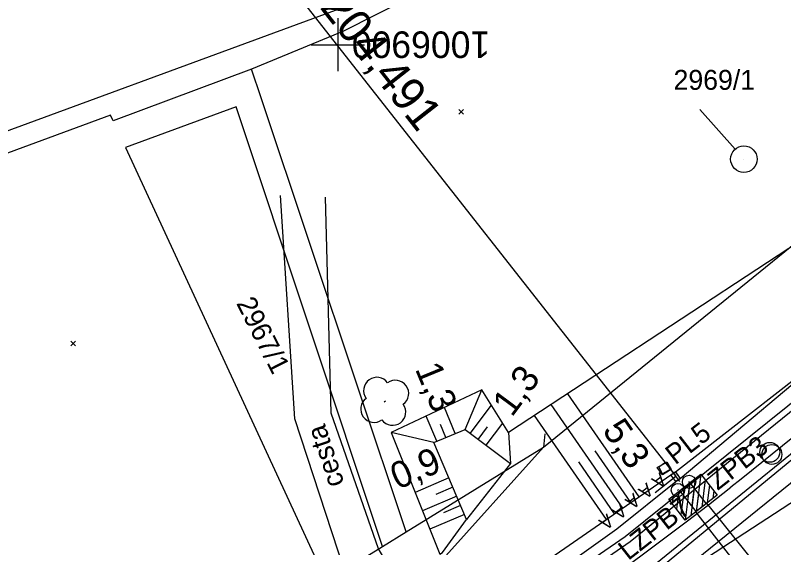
# Model space of a CAD drawing. Extents: x -800194 to -799078, y -1007177 to -1006597.
# Drawn here: x -799524.3 to -799466.4, y -1006937.9 to -1006897.8 of the extents above; entities that cross this region are included whole.
import ezdxf

# ---------------------------------------------------------------- set-up
doc = ezdxf.new("R2010")
doc.units = 0
for name, color, linetype in [('02_Osa_koleje', 7, 'Continuous'), ('_Vrstva 7 - Přesunutá', 7, 'Continuous'), ('Ramove udaje', 7, 'Continuous'), ('Vrstva 12', 7, 'Continuous'), ('Vrstva 27', 7, 'Continuous'), ('Vrstva 3', 7, 'Continuous'), ('Vrstva 37', 7, 'Continuous'), ('Vrstva 4', 7, 'Continuous'), ('Vrstva 48', 7, 'Continuous'), ('Vrstva 49', 7, 'Continuous'), ('Vrstva 50', 7, 'Continuous'), ('Vrstva 51', 7, 'Continuous'), ('Vrstva 53', 7, 'Continuous'), ('Vrstva 55', 7, 'Continuous'), ('Vrstva 56', 7, 'Continuous'), ('Vrstva 57', 7, 'Continuous'), ('Vrstva 6', 7, 'Continuous'), ('Vrstva 7', 7, 'Continuous')]:
    doc.layers.add(name, color=color, linetype=linetype)

msp = doc.modelspace()

# ---------------------------------------------------------------- linework, layer by layer
at = {"layer": '02_Osa_koleje'}
msp.add_lwpolyline([(-799465.749, -1006929.588), (-799466.523, -1006930.22), (-799467.3, -1006930.85), (-799468.078, -1006931.478), (-799468.859, -1006932.103), (-799469.642, -1006932.726), (-799470.426, -1006933.345)], dxfattribs=at)
msp.add_arc((-799651.022, -1006703.891), 292, 255.62486, 308.20516, dxfattribs=at)
at = {"layer": '_Vrstva 7 - Přesunutá'}
msp.add_circle((-799467.33, -1006930.875), 0.75, dxfattribs=at)
at = {"layer": 'Ramove udaje'}
for p, q in [((-799500, -1006898), (-799500, -1006902)), ((-799502, -1006900), (-799500, -1006900)), ((-799500, -1006900), (-799498, -1006900))]:
    msp.add_line(p, q, dxfattribs=at)
at = {"layer": 'Vrstva 12'}
for p, q in [((-799475.329, -1006931.448), (-799475.236, -1006931.455)), ((-799475.848, -1006931.802), (-799475.952, -1006931.866)), ((-799474.922, -1006932.004), (-799474.993, -1006932.013)), ((-799474.599, -1006932.171), (-799474.596, -1006932.171)), ((-799475.551, -1006932.322), (-799475.567, -1006932.408)), ((-799474.93, -1006932.406), (-799474.926, -1006932.405)), ((-799474.241, -1006932.695), (-799474.237, -1006932.694)), ((-799474.57, -1006932.917), (-799474.568, -1006932.916))]:
    msp.add_line(p, q, dxfattribs=at)
for points in [[(-799475.236, -1006931.455), (-799474.922, -1006932.004), (-799475.567, -1006932.408), (-799475.952, -1006931.866), (-799475.236, -1006931.455)], [(-799475.329, -1006931.448), (-799474.993, -1006932.013), (-799475.551, -1006932.322), (-799475.848, -1006931.802), (-799475.329, -1006931.448)], [(-799474.599, -1006932.171), (-799474.241, -1006932.695), (-799474.57, -1006932.917), (-799474.93, -1006932.406), (-799474.599, -1006932.171)], [(-799474.596, -1006932.171), (-799474.237, -1006932.694), (-799474.568, -1006932.916), (-799474.926, -1006932.405), (-799474.596, -1006932.171)]]:
    msp.add_lwpolyline(points, dxfattribs=at)
at = {"layer": 'Vrstva 27'}
for p, q in [((-799473.605, -1006932.963), (-799473.527, -1006932.901)), ((-799474.438, -1006933.585), (-799474.36, -1006933.523))]:
    msp.add_line(p, q, dxfattribs=at)
for centre in [(-799473.566, -1006932.932), (-799474.399, -1006933.554)]:
    msp.add_circle(centre, 0.5, dxfattribs=at)
at = {"layer": 'Vrstva 3'}
for p, q in [((-799473.103, -1006932.691), (-799473.352, -1006934.755)), ((-799472.686, -1006932.363), (-799473.025, -1006935.171)), ((-799473.918, -1006933.335), (-799474.181, -1006935.397)), ((-799473.499, -1006933.01), (-799473.857, -1006935.816)), ((-799473.521, -1006933.019), (-799473.68, -1006934.337)), ((-799472.359, -1006932.78), (-799472.608, -1006934.844)), ((-799472.031, -1006933.198), (-799472.19, -1006934.516)), ((-799474.338, -1006933.659), (-799474.506, -1006934.977)), ((-799473.938, -1006933.346), (-799474.007, -1006933.92)), ((-799473.175, -1006933.429), (-799473.438, -1006935.492)), ((-799472.85, -1006933.849), (-799473.018, -1006935.167)), ((-799471.704, -1006933.615), (-799471.773, -1006934.189)), ((-799474.757, -1006933.984), (-799474.83, -1006934.557)), ((-799472.525, -1006934.269), (-799472.599, -1006934.842)), ((-799442.19, -1006974.528), (-799473.063, -1006935.201))]:
    msp.add_line(p, q, dxfattribs=at)
for points in [[(-799471.451, -1006933.937), (-799473.025, -1006935.171), (-799474.26, -1006933.598), (-799472.686, -1006932.363)], [(-799472.275, -1006934.592), (-799473.857, -1006935.816), (-799475.081, -1006934.234), (-799473.499, -1006933.01)]]:
    msp.add_lwpolyline(points, close=True, dxfattribs=at)
msp.add_lwpolyline([(-799439.356, -1006972.379), (-799450.062, -1006959.03), (-799451.608, -1006960.27), (-799472.235, -1006934.552)], dxfattribs=at)
at = {"layer": 'Vrstva 37'}
for p, q in [((-799470.098, -1006907.873), (-799472.755, -1006904.883)), ((-799469.434, -1006908.621), (-799469.434, -1006908.621))]:
    msp.add_line(p, q, dxfattribs=at)
msp.add_circle((-799469.434, -1006908.621), 1, dxfattribs=at)
at = {"layer": 'Vrstva 4'}
for points in [[(-799510.394, -1006958.536), (-799498.027, -1006951.328), (-799477.988, -1006937.435), (-799460.33, -1006923.117), (-799451.862, -1006915.581), (-799443.604, -1006907.9), (-799435.444, -1006900.067), (-799428.64, -1006893.299), (-799422.817, -1006887.511), (-799415.998, -1006880.595), (-799408.158, -1006872.652), (-799401.02, -1006864.85)], [(-799509.248, -1006960.724), (-799497.456, -1006953.809), (-799476.495, -1006939.437), (-799458.707, -1006924.982), (-799450.277, -1006917.43), (-799441.932, -1006909.717), (-799433.783, -1006901.867), (-799426.9, -1006895.092), (-799421.037, -1006889.182), (-799414.218, -1006882.281), (-799406.443, -1006874.417), (-799398.609, -1006866.93)], [(-799511.236, -1006957.129), (-799499.236, -1006950.771), (-799498.598, -1006949.914), (-799498.679, -1006949.705), (-799496.151, -1006948.479), (-799496.251, -1006948.258), (-799490.687, -1006944.683), (-799490.497, -1006944.878), (-799488.249, -1006943.052), (-799488.105, -1006943.216), (-799486.269, -1006941.68), (-799478.997, -1006936.484), (-799474.568, -1006932.916), (-799474.237, -1006932.694), (-799461.519, -1006921.99), (-799452.935, -1006914.372), (-799444.695, -1006906.886), (-799436.579, -1006898.932), (-799429.629, -1006892.192), (-799429.07, -1006892.727), (-799423.479, -1006886.901), (-799416.56, -1006880.007), (-799417.085, -1006879.46), (-799415.349, -1006878.386)], [(-799510.726, -1006958.045), (-799497.901, -1006950.516), (-799478.36, -1006937.055), (-799461.534, -1006923.53), (-799452.128, -1006915.305), (-799443.894, -1006907.632), (-799435.739, -1006899.754), (-799428.922, -1006893.007), (-799423.223, -1006887.256), (-799416.277, -1006880.269), (-799414.896, -1006878.87)], [(-799509.087, -1006961.127), (-799497.277, -1006954.118), (-799476.183, -1006939.802), (-799458.586, -1006925.284), (-799449.914, -1006917.869), (-799441.499, -1006910.139), (-799433.371, -1006902.28), (-799426.451, -1006895.478), (-799420.657, -1006889.585), (-799413.85, -1006882.742), (-799412.388, -1006881.287)], [(-799507.817, -1006962.779), (-799497.104, -1006956.83), (-799497.4, -1006955.599), (-799497.585, -1006955.395), (-799495.628, -1006953.965), (-799495.505, -1006954.146), (-799493.236, -1006952.753), (-799493.081, -1006952.976), (-799487.499, -1006949.378), (-799487.565, -1006949.124), (-799485.713, -1006947.881), (-799485.847, -1006947.698), (-799483.858, -1006946.36), (-799483.734, -1006946.536), (-799483.686, -1006946.569), (-799482.647, -1006946.068), (-799475.489, -1006940.774), (-799457.684, -1006926.366)]]:
    msp.add_lwpolyline(points, dxfattribs=at)
at = {"layer": 'Vrstva 48'}
for p, q in [((-799477.319, -1006934.06), (-799482.69, -1006926.295)), ((-799491.172, -1006929.304), (-799491.98, -1006927.341)), ((-799490.032, -1006929.287), (-799488.444, -1006927.16)), ((-799478.552, -1006934.913), (-799483.943, -1006927.119)), ((-799492.559, -1006929.875), (-799493.339, -1006927.982)), ((-799479.786, -1006935.767), (-799485.197, -1006927.943)), ((-799491.865, -1006929.589), (-799492.262, -1006928.625)), ((-799488.83, -1006930.184), (-799487.586, -1006928.519)), ((-799489.431, -1006929.736), (-799488.723, -1006928.788)), ((-799477.935, -1006934.487), (-799480.626, -1006930.597)), ((-799479.169, -1006935.34), (-799481.87, -1006931.436)), ((-799491.636, -1006932.643), (-799494.189, -1006933.727)), ((-799491.343, -1006933.333), (-799492.626, -1006933.878)), ((-799491.05, -1006934.024), (-799493.632, -1006935.12)), ((-799490.757, -1006934.714), (-799492.055, -1006935.265)), ((-799490.463, -1006935.405), (-799493.074, -1006936.513))]:
    msp.add_line(p, q, dxfattribs=at)
at = {"layer": 'Vrstva 49'}
for p, q in [((-799490.889, -1006904.892), (-799490.535, -1006905.246)), ((-799490.889, -1006905.246), (-799490.535, -1006904.892)), ((-799520.095, -1006922.327), (-799519.741, -1006922.681)), ((-799520.095, -1006922.681), (-799519.741, -1006922.327)), ((-799520.095, -1006922.327), (-799519.741, -1006922.681)), ((-799520.095, -1006922.681), (-799519.741, -1006922.327)), ((-799490.423, -1006928.995), (-799489.168, -1006926.015)), ((-799492.773, -1006929.963), (-799495.987, -1006929.231)), ((-799492.124, -1006938.252), (-799490.308, -1006935.771))]:
    msp.add_line(p, q, dxfattribs=at)
for points in [[(-799429.125, -1006891.656), (-799433.133, -1006889.484), (-799437.572, -1006888.963), (-799439.693, -1006890.332), (-799461.15, -1006912.135), (-799487.142, -1006929.222), (-799487.006, -1006931.546), (-799490.308, -1006935.771)], [(-799490.09, -1006944.145), (-799488.194, -1006942.597), (-799488.011, -1006942.815), (-799488.011, -1006942.815), (-799486.419, -1006941.508), (-799486.269, -1006941.68), (-799484.618, -1006939.109), (-799474.926, -1006932.405), (-799474.596, -1006932.171), (-799461.519, -1006921.99), (-799452.935, -1006914.372), (-799445.566, -1006906.106), (-799432.588, -1006892.596), (-799429.125, -1006891.656)], [(-799486.865, -1006949.018), (-799484.86, -1006947.727), (-799485.016, -1006947.459), (-799485.713, -1006947.881), (-799483.734, -1006946.536), (-799483.686, -1006946.569), (-799483.396, -1006947.063), (-799482.389, -1006946.51), (-799482.647, -1006946.068), (-799475.489, -1006940.774), (-799464.892, -1006933.871), (-799456.989, -1006927.138), (-799455.117, -1006925.642), (-799440.165, -1006911.165), (-799428.918, -1006899.95), (-799428.299, -1006900.544), (-799427.466, -1006899.73), (-799428.131, -1006899.117), (-799426.509, -1006898.237), (-799425.17, -1006895.342)], [(-799487.142, -1006929.222), (-799489.168, -1006926.015), (-799495.987, -1006929.231), (-799492.323, -1006938.391), (-799492.124, -1006938.252)], [(-799490.308, -1006935.771), (-799492.773, -1006929.963), (-799490.423, -1006928.995), (-799487.006, -1006931.546)]]:
    msp.add_lwpolyline(points, dxfattribs=at)
at = {"layer": 'Vrstva 50'}
msp.add_line((-799496.517, -1006926.907), (-799496.403, -1006926.823), dxfattribs=at)
for centre, start, end in [((-799497.059, -1006926.062), 36.07189, 216.07189), ((-799495.662, -1006926.281), 306.07189, 126.07189), ((-799497.278, -1006927.459), 126.07189, 306.07189), ((-799495.881, -1006927.678), 216.07189, 36.07189)]:
    msp.add_arc(centre, 1, start, end, dxfattribs=at)
at = {"layer": 'Vrstva 51'}
for points in [[(-799487.284, -1006968.607), (-799490.087, -1006954.678), (-799499.499, -1006939.61), (-799503.236, -1006928.194), (-799504.313, -1006911.364)], [(-799484.495, -1006968.489), (-799487.918, -1006953.016), (-799496.949, -1006937.979), (-799500.5, -1006927.768), (-799500.929, -1006911.492)]]:
    msp.add_lwpolyline(points, dxfattribs=at)
at = {"layer": 'Vrstva 53'}
msp.add_lwpolyline([(-799559.64, -1006968.48), (-799519.68, -1006952.01), (-799500.87, -1006940.41), (-799496.64, -1006937.8), (-799494.85, -1006936.7), (-799484.519, -1006930.319), (-799457.99, -1006908.8), (-799435, -1006885.17), (-799430.26, -1006880.27), (-799425.53, -1006875.38), (-799422.55, -1006864.36), (-799390.88, -1006834), (-799358.35, -1006806.65), (-799352.29, -1006801.56), (-799330.91, -1006783.58), (-799314.235, -1006766.649)], dxfattribs=at)
at = {"layer": 'Vrstva 55'}
for p, q in [((-799496.64, -1006937.8), (-799494.85, -1006936.7)), ((-799500.87, -1006940.41), (-799496.64, -1006937.8))]:
    msp.add_line(p, q, dxfattribs=at)
for points in [[(-799439.06, -1006868.14), (-799466.75, -1006882.3), (-799482.8, -1006890.48), (-799499.57, -1006898.99), (-799506.49, -1006901.85)], [(-799494.85, -1006936.7), (-799484.52, -1006930.32), (-799457.99, -1006908.8), (-799435, -1006885.17)], [(-799586.79, -1006927.02), (-799561.07, -1006919.79), (-799500.17, -1006897.39), (-799498.58, -1006896.8)], [(-799506.49, -1006901.85), (-799516.91, -1006905.73), (-799517.11, -1006905.3), (-799557.12, -1006920.07)], [(-799494.85, -1006936.7), (-799505.77, -1006904), (-799506.49, -1006901.85)], [(-799496.64, -1006937.8), (-799507.65, -1006904.69), (-799515.98, -1006907.74), (-799500.87, -1006940.41)]]:
    msp.add_lwpolyline(points, dxfattribs=at)
at = {"layer": 'Vrstva 56'}
for p, q in [((-799484.415, -1006929.325), (-799484.519, -1006930.319)), ((-799484.52, -1006930.32), (-799492.32, -1006939.01))]:
    msp.add_line(p, q, dxfattribs=at)
at = {"layer": 'Vrstva 6'}
for p, q in [((-799505.431, -1006893.183), (-799474.557, -1006932.512)), ((-799474.248, -1006932.905), (-799474.866, -1006932.119)), ((-799476.114, -1006933.735), (-799474.557, -1006932.512))]:
    msp.add_line(p, q, dxfattribs=at)
at = {"layer": 'Vrstva 7'}
msp.add_circle((-799467.486, -1006930.71), 0.75, dxfattribs=at)

# ---------------------------------------------------------------- texts
at = {"layer": 'Ramove udaje'}
msp.add_text('1006900    ', height=2, rotation=180, dxfattribs=at).set_placement((-799488.53, -1006899))
at = {"layer": 'Vrstva 27'}
for s, p in [('ZPB3', (-799471.413, -1006933.627)), ('LZPB7', (-799478.141, -1006938.908))]:
    msp.add_text(s, height=1.5, rotation=38.13277, dxfattribs=at).set_placement(p)
at = {"layer": 'Vrstva 48'}
for s, rotation, p in [('1,3', 292.38749, (-799494.208, -1006924.423)), ('1,3', 53.2564, (-799486.904, -1006928.121)), ('5,3', 304.67178, (-799480.14, -1006929.068)), ('0,9', 22.99708, (-799495.498, -1006933.548))]:
    msp.add_text(s, height=2, rotation=rotation, dxfattribs=at).set_placement(p)
at = {"layer": 'Vrstva 51'}
msp.add_text('cesta', height=1.5, rotation=108.12573, dxfattribs=at).set_placement((-799499.492, -1006933.062))
at = {"layer": 'Vrstva 57'}
msp.add_text('2969/1', height=1.5, dxfattribs=at).set_placement((-799474.73, -1006903.4))
msp.add_text('2967/1', height=1.5, rotation=297, dxfattribs=at).set_placement((-799507.67, -1006919.476))
at = {"layer": 'Vrstva 6'}
for s, height, rotation, p in [('km 204,491', 2.5, 308.13277, (-799504.737, -1006892.946)), ('PL5', 1.5, 37.72532, (-799474.604, -1006931.701)), ('  A A A A A ', 1, 218.13277, (-799475.174, -1006931.725))]:
    msp.add_text(s, height=height, rotation=rotation, dxfattribs=at).set_placement(p)

doc.saveas('drawing.dxf')
